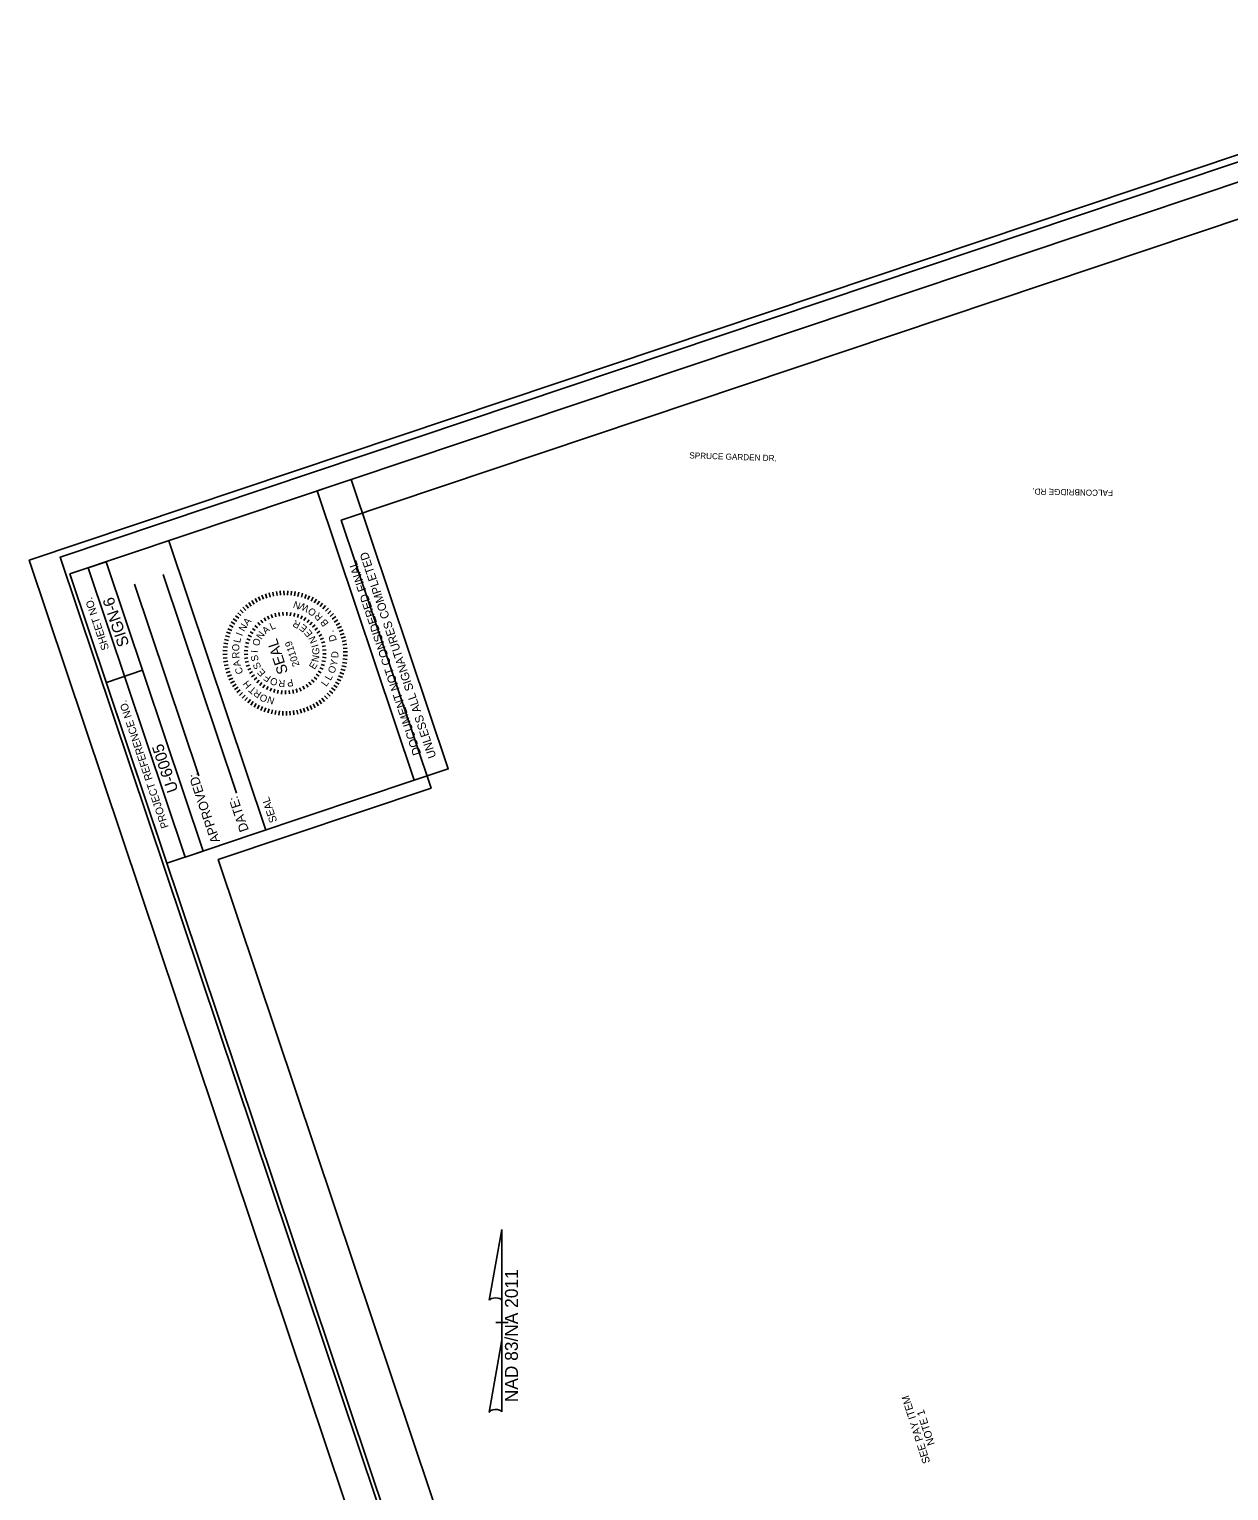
# Model space of a CAD drawing. Extents: x 1615436 to 1617010, y 903110 to 905055.
# Drawn here: x 1615436 to 1616223, y 904096 to 905055 of the extents above; entities that cross this region are included whole.
import ezdxf

# ---------------------------------------------------------------- set-up
doc = ezdxf.new("R2010")
doc.units = 0
for name, color, linetype in [('CTL Primary Horizontal and Vertical CELL', 7, 'Continuous'), ('CTL Primary Horizontal and Vertical Cogo Number', 7, 'Continuous'), ('CTL Secondary Horizontal and Vertical Cogo Number', 7, 'Continuous'), ('Default', 7, 'Continuous'), ('Exist DTM Regular Point Cogo Number', 7, 'Continuous'), ('Exist Roads EOP Other Cogo Point CELL', 7, 'Continuous'), ('Exist Roads EOT Cogo Number', 7, 'Continuous'), ('Exist Structure Minor Pipes CMP 15 Inch Cogo Number', 7, 'Continuous'), ('Exist Structure Minor Pipes CMP 15 Inch Cogo Point CELL', 7, 'Continuous'), ('Exist Structure Minor Pipes RCP 15 Inch Cogo Number', 7, 'Continuous'), ('Exist Utilities Sanitary Sewer Manhole CELL', 7, 'Continuous'), ('Exist Utilities Sanitary Sewer Manhole Cogo Number', 7, 'Continuous')]:
    doc.layers.add(name, color=color, linetype=linetype)

msp = doc.modelspace()

# ---------------------------------------------------------------- linework, layer by layer
at = {"layer": 'CTL Primary Horizontal and Vertical CELL'}
msp.add_lwpolyline([(1616986.86, 903464.68), (1616457.04, 905044.17), (1615456.82, 904708.68), (1615986.63, 903129.17)], close=True, dxfattribs=at)
at = {"layer": 'CTL Primary Horizontal and Vertical Cogo Number'}
msp.add_lwpolyline([(1617009.96, 903458.71), (1616474.57, 905054.81), (1615436.42, 904706.58), (1615971.81, 903110.48)], close=True, dxfattribs=at)
at = {"layer": 'Default'}
for p, q in [((1615584.58, 904681.52), (1615585.92, 904679.08)), ((1615586.78, 904682.64), (1615587.97, 904680.12)), ((1615589.04, 904683.63), (1615590.08, 904681.05)), ((1615591.36, 904684.49), (1615592.24, 904681.84)), ((1615593.72, 904685.2), (1615594.45, 904682.51)), ((1615596.12, 904685.76), (1615596.68, 904683.04)), ((1615598.56, 904686.19), (1615598.95, 904683.43)), ((1615601.01, 904686.46), (1615601.24, 904683.69)), ((1615603.48, 904686.59), (1615603.54, 904683.8)), ((1615605.94, 904686.56), (1615605.83, 904683.78)), ((1615608.41, 904686.39), (1615608.13, 904683.62)), ((1615610.86, 904686.07), (1615610.41, 904683.32)), ((1615613.28, 904685.6), (1615612.67, 904682.88)), ((1615615.67, 904684.99), (1615614.9, 904682.31)), ((1615618.02, 904684.23), (1615617.09, 904681.61)), ((1615620.32, 904683.33), (1615619.23, 904680.77)), ((1615622.56, 904682.3), (1615621.32, 904679.8)), ((1615624.74, 904681.13), (1615623.35, 904678.72)), ((1615573.17, 904672.19), (1615575.3, 904670.39)), ((1615574.83, 904674.02), (1615576.84, 904672.09)), ((1615576.59, 904675.75), (1615578.48, 904673.7)), ((1615578.45, 904677.37), (1615580.22, 904675.21)), ((1615580.41, 904678.88), (1615582.04, 904676.61)), ((1615582.46, 904680.26), (1615583.94, 904677.9)), ((1615597.65, 904671.82), (1615598.22, 904669.57)), ((1615600.47, 904670.04), (1615600.11, 904672.33)), ((1615602.79, 904672.62), (1615602.92, 904670.3)), ((1615605.39, 904672.64), (1615605.3, 904670.32)), ((1615607.98, 904672.41), (1615607.67, 904670.11)), ((1615610.54, 904671.93), (1615610.01, 904669.67)), ((1615613.05, 904671.21), (1615612.29, 904669.01)), ((1615626.84, 904679.83), (1615625.31, 904677.51)), ((1615628.86, 904678.41), (1615627.19, 904676.18)), ((1615630.79, 904676.87), (1615628.99, 904674.74)), ((1615632.62, 904675.21), (1615630.69, 904673.2)), ((1615634.35, 904673.45), (1615632.3, 904671.56)), ((1615635.97, 904671.59), (1615633.81, 904669.82)), ((1615566.71, 904661.72), (1615569.27, 904660.63)), ((1615567.74, 904663.96), (1615570.23, 904662.72)), ((1615568.91, 904666.14), (1615571.32, 904664.75)), ((1615570.21, 904668.24), (1615572.53, 904666.71)), ((1615571.63, 904670.26), (1615573.86, 904668.59)), ((1615582.77, 904661.89), (1615584.63, 904660.5)), ((1615584.43, 904663.89), (1615586.15, 904662.33)), ((1615586.28, 904665.73), (1615587.84, 904664.01)), ((1615588.3, 904667.38), (1615589.68, 904665.51)), ((1615590.46, 904668.82), (1615591.66, 904666.83)), ((1615592.76, 904670.05), (1615593.75, 904667.96)), ((1615595.16, 904671.06), (1615595.95, 904668.87)), ((1615615.46, 904670.25), (1615614.5, 904668.14)), ((1615617.78, 904669.06), (1615616.62, 904667.05)), ((1615619.97, 904667.65), (1615618.62, 904665.76)), ((1615622.01, 904666.04), (1615620.48, 904664.28)), ((1615623.89, 904664.23), (1615622.2, 904662.64)), ((1615625.59, 904662.26), (1615623.75, 904660.83)), ((1615637.47, 904669.63), (1615635.21, 904668)), ((1615638.86, 904667.58), (1615636.5, 904666.1)), ((1615640.11, 904665.46), (1615637.68, 904664.12)), ((1615641.24, 904663.26), (1615638.72, 904662.07)), ((1615563.97, 904652.26), (1615566.72, 904651.81)), ((1615564.44, 904654.68), (1615567.16, 904654.07)), ((1615565.05, 904657.07), (1615567.73, 904656.3)), ((1615565.81, 904659.42), (1615568.43, 904658.49)), ((1615578.26, 904652.58), (1615580.51, 904651.99)), ((1615579.05, 904655.06), (1615581.23, 904654.25)), ((1615580.07, 904657.45), (1615582.16, 904656.44)), ((1615581.31, 904659.74), (1615583.3, 904658.53)), ((1615627.08, 904660.13), (1615625.12, 904658.88)), ((1615628.37, 904657.86), (1615626.29, 904656.82)), ((1615629.43, 904655.49), (1615627.26, 904654.65)), ((1615630.25, 904653.02), (1615628.02, 904652.39)), ((1615642.23, 904661), (1615639.65, 904659.96)), ((1615643.08, 904658.68), (1615640.44, 904657.8)), ((1615643.8, 904656.32), (1615641.11, 904655.59)), ((1615644.36, 904653.92), (1615641.64, 904653.36)), ((1615563.45, 904644.88), (1615566.24, 904644.94)), ((1615563.47, 904647.34), (1615566.26, 904647.23)), ((1615563.58, 904642.41), (1615566.35, 904642.64)), ((1615563.65, 904649.81), (1615566.42, 904649.53)), ((1615577.39, 904644.84), (1615579.72, 904644.92)), ((1615577.43, 904647.44), (1615579.75, 904647.29)), ((1615577.61, 904642.24), (1615579.91, 904642.55)), ((1615577.73, 904650.03), (1615580.02, 904649.66)), ((1615630.83, 904650.48), (1615628.55, 904650.07)), ((1615631.09, 904642.7), (1615628.78, 904642.96)), ((1615628.86, 904647.7), (1615631.18, 904647.88)), ((1615631.26, 904645.3), (1615628.93, 904645.34)), ((1615644.79, 904651.48), (1615642.03, 904651.09)), ((1615645.06, 904649.03), (1615642.29, 904648.8)), ((1615645.16, 904644.1), (1615642.38, 904644.21)), ((1615645.19, 904646.56), (1615642.4, 904646.5)), ((1615563.85, 904639.96), (1615566.61, 904640.35)), ((1615564.28, 904637.53), (1615567, 904638.08)), ((1615564.84, 904635.12), (1615567.53, 904635.85)), ((1615565.55, 904632.76), (1615568.2, 904633.64)), ((1615578.07, 904639.68), (1615580.33, 904640.2)), ((1615578.77, 904637.18), (1615580.97, 904637.91)), ((1615580.97, 904637.91), (1615578.77, 904637.18)), ((1615579.72, 904634.75), (1615581.83, 904635.69)), ((1615580.89, 904632.43), (1615582.91, 904633.57)), ((1615627.97, 904632.83), (1615625.94, 904633.94)), ((1615629.11, 904635.17), (1615626.97, 904636.08)), ((1615630.01, 904637.61), (1615627.8, 904638.31)), ((1615630.67, 904640.13), (1615628.4, 904640.61)), ((1615642.83, 904632.02), (1615640.21, 904632.95)), ((1615643.59, 904634.37), (1615640.91, 904635.14)), ((1615644.2, 904636.76), (1615641.48, 904637.37)), ((1615644.67, 904639.18), (1615641.92, 904639.63)), ((1615644.99, 904641.63), (1615642.22, 904641.91)), ((1615566.41, 904630.44), (1615568.99, 904631.48)), ((1615567.4, 904628.18), (1615569.92, 904629.37)), ((1615568.52, 904625.98), (1615570.96, 904627.33)), ((1615569.78, 904623.86), (1615572.14, 904625.34)), ((1615571.16, 904621.81), (1615573.43, 904623.44)), ((1615582.28, 904630.23), (1615584.18, 904631.56)), ((1615583.88, 904628.17), (1615585.64, 904629.68)), ((1615585.67, 904626.28), (1615587.28, 904627.95)), ((1615587.63, 904624.57), (1615589.07, 904626.39)), ((1615589.75, 904623.06), (1615591.01, 904625.01)), ((1615592.01, 904621.76), (1615593.07, 904623.83)), ((1615617.04, 904621.98), (1615615.95, 904624.02)), ((1615619.28, 904623.31), (1615617.99, 904625.24)), ((1615621.37, 904624.86), (1615619.9, 904626.66)), ((1615623.3, 904626.61), (1615621.66, 904628.25)), ((1615625.06, 904628.52), (1615623.27, 904630.01)), ((1615626.62, 904630.61), (1615624.7, 904631.91)), ((1615638.43, 904623.2), (1615636.11, 904624.73)), ((1615639.73, 904625.3), (1615637.32, 904626.69)), ((1615640.9, 904627.48), (1615638.4, 904628.72)), ((1615641.93, 904629.72), (1615639.37, 904630.81)), ((1615572.67, 904619.85), (1615574.83, 904621.62)), ((1615574.29, 904617.99), (1615576.34, 904619.88)), ((1615576.02, 904616.23), (1615577.95, 904618.24)), ((1615577.85, 904614.57), (1615579.65, 904616.7)), ((1615579.78, 904613.03), (1615581.45, 904615.26)), ((1615581.8, 904611.61), (1615583.33, 904613.93)), ((1615594.37, 904620.68), (1615595.23, 904622.84)), ((1615596.84, 904619.84), (1615597.49, 904622.07)), ((1615599.37, 904619.24), (1615599.8, 904621.52)), ((1615601.95, 904618.88), (1615602.15, 904621.2)), ((1615604.55, 904618.78), (1615604.53, 904621.1)), ((1615607.15, 904618.93), (1615606.9, 904621.24)), ((1615609.72, 904619.33), (1615609.25, 904621.6)), ((1615612.24, 904619.97), (1615611.56, 904622.19)), ((1615614.69, 904620.86), (1615613.8, 904623)), ((1615628.23, 904612.56), (1615626.6, 904614.83)), ((1615630.19, 904614.07), (1615628.42, 904616.23)), ((1615632.05, 904615.69), (1615630.16, 904617.74)), ((1615633.81, 904617.42), (1615631.8, 904619.35)), ((1615635.47, 904619.25), (1615633.34, 904621.05)), ((1615637.01, 904621.18), (1615634.78, 904622.85)), ((1615583.9, 904610.31), (1615585.29, 904612.72)), ((1615586.08, 904609.14), (1615587.32, 904611.64)), ((1615588.32, 904608.11), (1615589.41, 904610.67)), ((1615590.62, 904607.21), (1615591.55, 904609.83)), ((1615592.97, 904606.45), (1615593.74, 904609.13)), ((1615595.36, 904605.84), (1615595.97, 904608.56)), ((1615597.78, 904605.37), (1615598.23, 904608.12)), ((1615600.23, 904605.05), (1615600.51, 904607.82)), ((1615602.7, 904604.88), (1615602.81, 904607.66)), ((1615605.16, 904604.85), (1615605.1, 904607.64)), ((1615607.63, 904604.98), (1615607.4, 904607.75)), ((1615610.08, 904605.25), (1615609.69, 904608.01)), ((1615612.52, 904605.68), (1615611.96, 904608.4)), ((1615614.92, 904606.24), (1615614.19, 904608.93)), ((1615617.28, 904606.96), (1615616.4, 904609.6)), ((1615619.6, 904607.81), (1615618.56, 904610.39)), ((1615621.86, 904608.8), (1615620.67, 904611.32)), ((1615624.06, 904609.93), (1615622.71, 904612.36)), ((1615626.18, 904611.18), (1615624.7, 904613.54))]:
    msp.add_line(p, q, dxfattribs=at)
at = {"layer": 'Exist DTM Regular Point Cogo Number'}
msp.add_lwpolyline([(1616672.58, 903656.2), (1616919.77, 903656.8), (1616590.65, 904611.24), (1616386.84, 904624.44), (1616334.81, 904821.64), (1616466, 905009.57), (1615641.09, 904732.87), (1615700.02, 904557.19), (1615560.35, 904510.33), (1615954.19, 903336.21)], close=True, dxfattribs=at)
at = {"layer": 'Exist Roads EOP Other Cogo Point CELL'}
for p, q in [((1615738.18, 904221.45), (1615746.38, 904267.8)), ((1615746.43, 904267.8), (1615746.38, 904267.8)), ((1615746.43, 904267.8), (1615746.38, 904267.8)), ((1615746.43, 904267.8), (1615746.43, 904220)), ((1615746.43, 904195.2), (1615746.43, 904221.4)), ((1615746.43, 904220), (1615746.43, 904221.35)), ((1615742.43, 904206.8), (1615742.38, 904206.8)), ((1615745.98, 904206.8), (1615742.43, 904206.8)), ((1615742.48, 904206.8), (1615750.48, 904206.8)), ((1615746.43, 904195.2), (1615738.08, 904147.95)), ((1615746.48, 904148.15), (1615746.43, 904195.2))]:
    msp.add_line(p, q, dxfattribs=at)
for centre, start_param, end_param in [((1615742.32, 904220.95), 0.216388, 2.908219), ((1615742.32, 904147.78), 0.201328, 3.141593)]:
    msp.add_ellipse(centre, major_axis=(4.23, -0.03), ratio=0.461098, start_param=start_param, end_param=end_param, dxfattribs=at)
at = {"layer": 'Exist Roads EOT Cogo Number'}
msp.add_lwpolyline([(1615689.01, 904562.36), (1615625.38, 904752.06), (1615647.65, 904759.53), (1615711.28, 904569.83)], close=True, dxfattribs=at)
at = {"layer": 'Exist Structure Minor Pipes CMP 15 Inch Cogo Point CELL'}
for p, q in [((1615547.63, 904565.24), (1615505.46, 904690.97)), ((1615572.45, 904553.86), (1615524.33, 904697.3))]:
    msp.add_line(p, q, dxfattribs=at)
at = {"layer": 'Exist Structure Minor Pipes RCP 15 Inch Cogo Number'}
for p, q in [((1615538.66, 904511.93), (1615475.05, 904701.6)), ((1615550.54, 904515.93), (1615486.9, 904705.57)), ((1615550.54, 904515.93), (1615486.9, 904705.57)), ((1615487.07, 904626.5), (1615510.76, 904634.49))]:
    msp.add_line(p, q, dxfattribs=at)
for points in [[(1615463.14, 904697.64), (1615940.18, 903275.48), (1616935.67, 903609.4), (1616458.64, 905031.54)], [(1615526.76, 904507.95), (1615463.14, 904697.64), (1615486.9, 904705.57), (1615550.54, 904515.93)]]:
    msp.add_lwpolyline(points, close=True, dxfattribs=at)
at = {"layer": 'Exist Utilities Sanitary Sewer Manhole Cogo Number'}
for p, q in [((1615625.38, 904752.06), (1615689.01, 904562.36)), ((1615591.68, 904529.71), (1615528.05, 904719.41)), ((1615689.01, 904562.36), (1615583.39, 904526.93)), ((1615583.39, 904526.93), (1615538.66, 904511.93))]:
    msp.add_line(p, q, dxfattribs=at)

# ---------------------------------------------------------------- texts
at = {"layer": 'CTL Secondary Horizontal and Vertical Cogo Number'}
for s, p in [('SIGN-6', (1615502.13, 904651.36)), ('U-6005', (1615534.29, 904555.69))]:
    msp.add_text(s, height=7.5, rotation=108.54318, dxfattribs=at).set_placement(p)
at = {"layer": 'Default'}
for s, height, rotation, p in [('N', 4.64, 160.69721, (1615614.83, 904678.51)), ('W', 4.64, 151.81458, (1615620.49, 904676.3)), ('O', 4.64, 142.93195, (1615625.24, 904673.07)), ('R', 4.64, 134.10934, (1615629.33, 904669.58)), ('N', 4.64, 58.77478, (1615577.4, 904659.45)), ('A', 4.64, 49.00725, (1615579.68, 904663.44)), ('A', 4.64, 39.65705, (1615591.49, 904657.88)), ('L', 4.64, 24.3608, (1615595.37, 904660.76)), ('R', 4.64, 153.05505, (1615614.73, 904665.59)), ('E', 4.64, 139.28396, (1615619.2, 904662.42)), ('E', 4.64, 129.29808, (1615622.58, 904658.53)), ('B', 4.64, 125.10677, (1615633.03, 904665.17)), ('L', 4.64, 77.64472, (1615574.69, 904652.15)), ('I', 4.64, 68.06925, (1615576.06, 904656.55)), ('O', 4.64, 70.24954, (1615586.88, 904649.88)), ('N', 4.64, 54.9533, (1615588.69, 904654.26)), ('SEAL', 6.965, 108.49016, (1615606.3, 904633.22)), ('20119', 4.64, 108.49016, (1615613.79, 904637.73)), ('N', 4.64, 113.90601, (1615625.43, 904653.29)), ('D', 4.64, 104.58011, (1615638.16, 904653.93)), ('.', 4.64, 112.32246, (1615636.34, 904659.5)), ('O', 4.64, 90.781, (1615574.23, 904647.01)), ('R', 4.64, 93.83781, (1615574.39, 904642.33)), ('I', 4.64, 85.54579, (1615586.35, 904645.76)), ('S', 4.64, 100.84203, (1615586.97, 904640.77)), ('I', 4.64, 106.27635, (1615626.28, 904650.25)), ('N', 4.64, 79.41532, (1615626, 904639.54)), ('G', 4.64, 88.18155, (1615626.62, 904644.54)), ('D', 4.64, 86.7848, (1615639.06, 904642.34)), ('A', 4.64, 105.84712, (1615575.3, 904637.45)), ('C', 4.64, 105.84712, (1615576.82, 904632.61)), ('S', 4.64, 116.13828, (1615588.8, 904636.49)), ('E', 4.64, 131.43453, (1615591.7, 904632.87)), ('E', 4.64, 58.56025, (1615623.57, 904634.62)), ('O', 4.64, 69.13974, (1615636.38, 904631.9)), ('Y', 4.64, 77.81232, (1615638.1, 904636.92)), ('H', 4.64, 129.55781, (1615582.58, 904624.8)), ('T', 4.64, 138.98976, (1615585.68, 904621.9)), ('F', 4.64, 146.73077, (1615595.36, 904630.18)), ('O', 4.64, 162.02702, (1615599.89, 904628.44)), ('R', 4.64, 177.32326, (1615604.42, 904628.02)), ('P', 4.64, 192.61951, (1615609.01, 904628.81)), ('L', 4.64, 52.42517, (1615631.16, 904623.41)), ('L', 4.64, 60.49699, (1615634.02, 904627.39)), ('R', 4.64, 147.15072, (1615589.13, 904619.76)), ('O', 4.64, 160.20745, (1615593.16, 904617.56)), ('N', 4.64, 162.16688, (1615597.72, 904616.28)), ('SEE PAY ITEM', 5, 107.75176, (1616027.42, 904115.18)), ('NOTE 1', 5, 107.75176, (1616030.5, 904127.06))]:
    msp.add_text(s, height=height, rotation=rotation, dxfattribs=at).set_placement(p)
at = {"layer": 'Exist Roads EOP Other Cogo Point CELL'}
msp.add_text('NAD 83/NA 2011', height=8.5, rotation=90, dxfattribs=at).set_placement((1615756.95, 904154.49))
at = {"layer": 'Exist Roads EOT Cogo Number'}
for s, p in [('UNLESS ALL SIGNATURES COMPLETED', (1615703.5, 904577.78)), ('DOCUMENT NOT CONSIDERED FINAL', (1615693.55, 904579.79))]:
    msp.add_text(s, height=5.4984, rotation=108.54317, dxfattribs=at).set_placement(p)
at = {"layer": 'Exist Structure Minor Pipes CMP 15 Inch Cogo Number'}
for s, p in [('APPROVED:', (1615561.72, 904522.39)), ('DATE:', (1615580.52, 904529.67))]:
    msp.add_text(s, height=6.11, rotation=108.53811, dxfattribs=at).set_placement(p)
at = {"layer": 'Exist Structure Minor Pipes CMP 15 Inch Cogo Point CELL'}
msp.add_text('SEAL', height=5.094, rotation=108.53811, dxfattribs=at).set_placement((1615599.16, 904535.41))
at = {"layer": 'Exist Structure Minor Pipes RCP 15 Inch Cogo Number'}
for s, height, p in [('SHEET NO.', 5, (1615488.91, 904648.58)), ('PROJECT REFERENCE NO.', 5.0001, (1615527.97, 904531.77))]:
    msp.add_text(s, height=height, rotation=108.54318, dxfattribs=at).set_placement(p)
at = {"layer": 'Exist Utilities Sanitary Sewer Manhole CELL'}
for s, rotation, p in [('SPRUCE GARDEN DR.', 358.10831, (1615869.33, 904773.41)), ('FALCONBRIDGE RD.', 178.88474, (1616147.27, 904752.65))]:
    msp.add_text(s, height=4, rotation=rotation, dxfattribs=at).set_placement(p)

doc.saveas('drawing.dxf')
